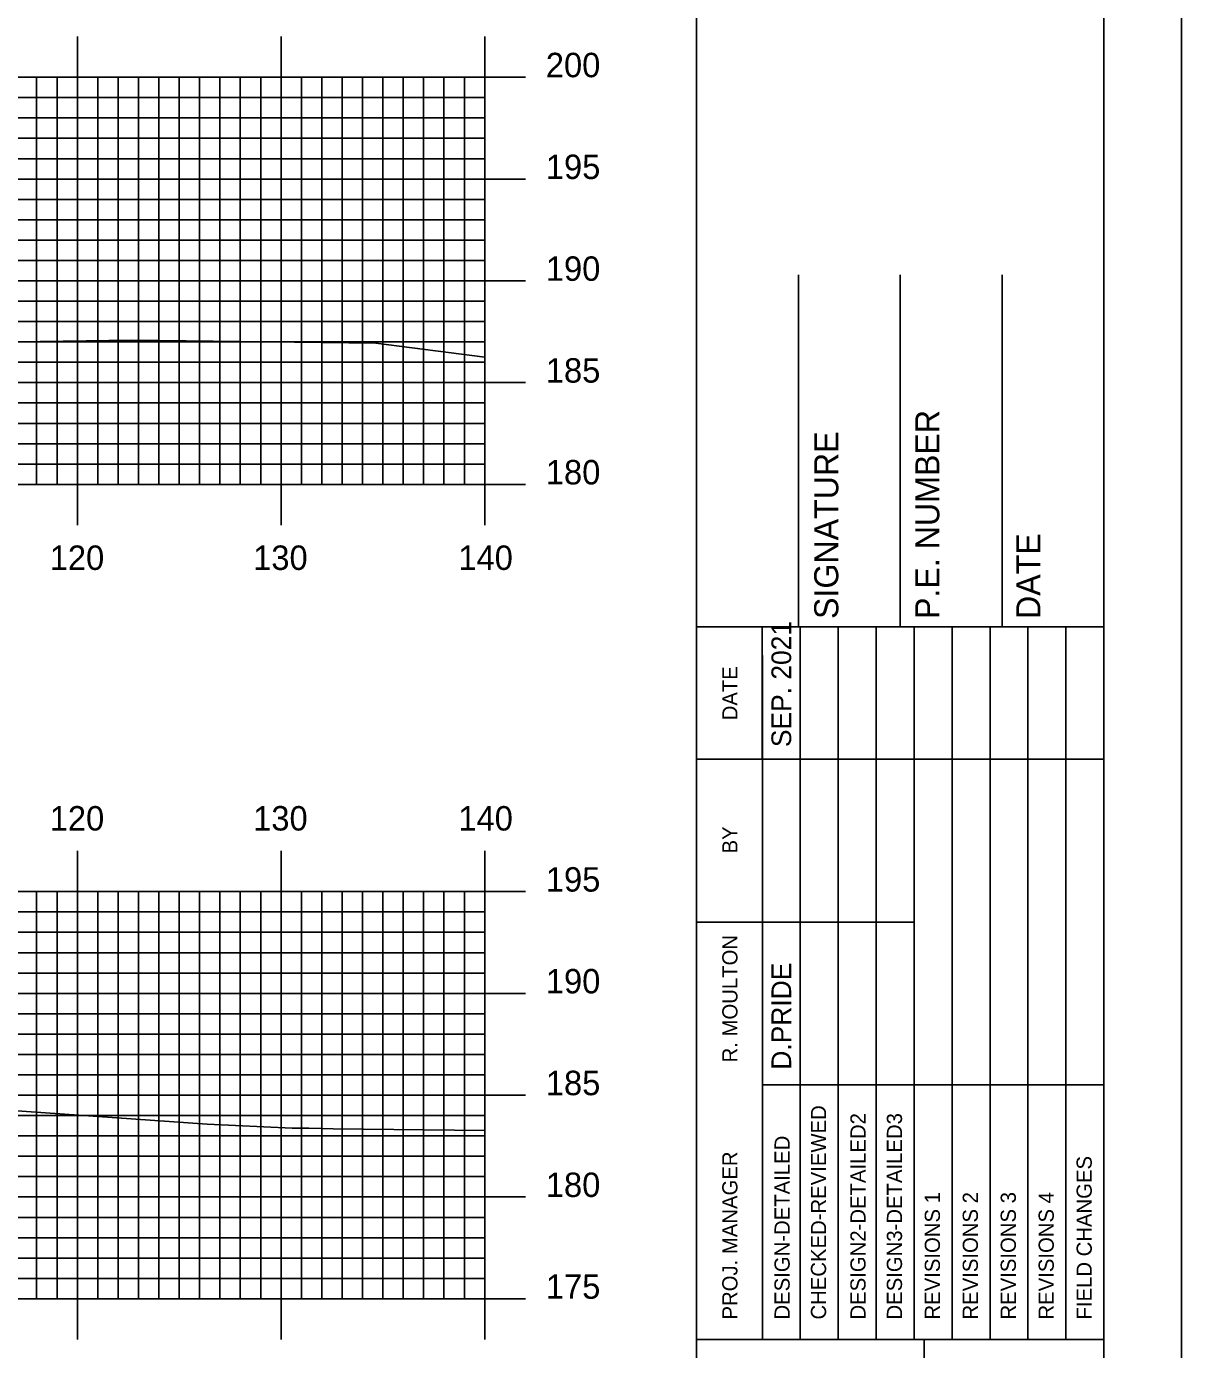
# Model space of a CAD drawing. Extents: x 1825147 to 1825490, y 442591 to 442811.
# Drawn here: x 1825429.9 to 1825486.6, y 442686.2 to 442751.2 of the extents above; entities that cross this region are included whole.
import ezdxf

# ---------------------------------------------------------------- set-up
doc = ezdxf.new("R2010")
doc.units = 0
for name, color, linetype in [('BORDER', 7, 'Continuous'), ('H_V ANNOTATION', 7, 'Continuous'), ('MAJOR', 7, 'Continuous'), ('MINOR', 7, 'Continuous'), ('PLOT BOUNDARY', 7, 'Continuous'), ('S_Roadway_Centerline', 7, 'Continuous')]:
    doc.layers.add(name, color=color, linetype=linetype)

msp = doc.modelspace()

# ---------------------------------------------------------------- linework, layer by layer
at = {"layer": 'BORDER'}
for p, q in [((1825462.761, 442596.665), (1825462.761, 442806.665)), ((1825467.761, 442721.671), (1825467.761, 442738.966)), ((1825472.761, 442721.671), (1825472.761, 442738.966)), ((1825477.761, 442721.671), (1825477.761, 442738.966)), ((1825462.761, 442721.671), (1825482.761, 442721.671)), ((1825462.761, 442686.671), (1825482.761, 442686.671)), ((1825473.943, 442616.671), (1825473.943, 442686.671))]:
    msp.add_line(p, q, dxfattribs=at)
msp.add_lwpolyline([(1825162.761, 442596.665), (1825482.761, 442596.665), (1825482.761, 442806.665), (1825162.761, 442806.665)], close=True, dxfattribs=at)
for points in [[(1825465.991, 442715.171), (1825465.991, 442721.671)], [(1825467.856, 442686.677), (1825467.856, 442721.671)], [(1825469.719, 442721.671), (1825469.719, 442686.677)], [(1825471.583, 442686.677), (1825471.583, 442721.671)], [(1825473.446, 442686.677), (1825473.446, 442721.671)], [(1825475.309, 442686.677), (1825475.309, 442721.671)], [(1825477.173, 442686.677), (1825477.173, 442721.671)], [(1825479.036, 442686.677), (1825479.036, 442721.671)], [(1825480.899, 442686.677), (1825480.899, 442721.671)], [(1825465.993, 442686.677), (1825465.993, 442720.259)], [(1825462.761, 442715.171), (1825482.761, 442715.171)], [(1825462.761, 442707.171), (1825465.993, 442707.171)], [(1825465.991, 442707.171), (1825473.444, 442707.171)], [(1825465.991, 442699.171), (1825482.761, 442699.171)]]:
    msp.add_lwpolyline(points, dxfattribs=at)
at = {"layer": 'MAJOR'}
for p, q in [((1825432.361, 442750.669), (1825432.361, 442748.665)), ((1825442.361, 442750.669), (1825442.361, 442748.665)), ((1825452.361, 442750.669), (1825452.361, 442748.665)), ((1825312.361, 442748.665), (1825452.361, 442748.665)), ((1825312.361, 442748.665), (1825452.361, 442748.665)), ((1825432.361, 442728.665), (1825432.361, 442748.665)), ((1825442.361, 442728.665), (1825442.361, 442748.665)), ((1825454.365, 442748.665), (1825450.357, 442748.665)), ((1825452.361, 442728.665), (1825452.361, 442748.665)), ((1825452.361, 442728.665), (1825452.361, 442748.665)), ((1825312.361, 442743.665), (1825452.361, 442743.665)), ((1825454.365, 442743.665), (1825450.357, 442743.665)), ((1825312.361, 442738.665), (1825452.361, 442738.665)), ((1825454.365, 442738.665), (1825450.357, 442738.665)), ((1825312.361, 442733.665), (1825452.361, 442733.665)), ((1825454.365, 442733.665), (1825450.357, 442733.665)), ((1825312.361, 442728.665), (1825452.361, 442728.665)), ((1825312.361, 442728.665), (1825452.361, 442728.665)), ((1825432.361, 442726.661), (1825432.361, 442728.665)), ((1825442.361, 442726.661), (1825442.361, 442728.665)), ((1825454.365, 442728.665), (1825450.357, 442728.665)), ((1825452.361, 442726.661), (1825452.361, 442728.665)), ((1825432.361, 442710.669), (1825432.361, 442708.665)), ((1825442.361, 442710.669), (1825442.361, 442708.665)), ((1825452.361, 442710.669), (1825452.361, 442708.665)), ((1825172.361, 442708.665), (1825452.361, 442708.665)), ((1825172.361, 442708.665), (1825452.361, 442708.665)), ((1825172.361, 442708.665), (1825452.361, 442708.665)), ((1825432.361, 442688.665), (1825432.361, 442708.665)), ((1825432.361, 442688.665), (1825432.361, 442708.665)), ((1825442.361, 442688.665), (1825442.361, 442708.665)), ((1825442.361, 442688.665), (1825442.361, 442708.665)), ((1825454.365, 442708.665), (1825450.357, 442708.665)), ((1825452.361, 442688.665), (1825452.361, 442708.665)), ((1825452.361, 442688.665), (1825452.361, 442708.665)), ((1825452.361, 442688.665), (1825452.361, 442708.665)), ((1825172.361, 442703.665), (1825452.361, 442703.665)), ((1825172.361, 442703.665), (1825452.361, 442703.665)), ((1825454.365, 442703.665), (1825450.357, 442703.665)), ((1825172.361, 442698.665), (1825452.361, 442698.665)), ((1825172.361, 442698.665), (1825452.361, 442698.665)), ((1825454.365, 442698.665), (1825450.357, 442698.665)), ((1825172.361, 442693.665), (1825452.361, 442693.665)), ((1825172.361, 442693.665), (1825452.361, 442693.665)), ((1825454.365, 442693.665), (1825450.357, 442693.665)), ((1825172.361, 442688.665), (1825452.361, 442688.665)), ((1825172.361, 442688.665), (1825452.361, 442688.665)), ((1825172.361, 442688.665), (1825452.361, 442688.665)), ((1825432.361, 442686.661), (1825432.361, 442688.665)), ((1825442.361, 442686.661), (1825442.361, 442688.665)), ((1825454.365, 442688.665), (1825450.357, 442688.665)), ((1825452.361, 442686.661), (1825452.361, 442688.665))]:
    msp.add_line(p, q, dxfattribs=at)
at = {"layer": 'MINOR'}
for p, q in [((1825430.361, 442728.665), (1825430.361, 442748.665)), ((1825431.361, 442728.665), (1825431.361, 442748.665)), ((1825433.361, 442728.665), (1825433.361, 442748.665)), ((1825434.361, 442728.665), (1825434.361, 442748.665)), ((1825435.361, 442728.665), (1825435.361, 442748.665)), ((1825436.361, 442728.665), (1825436.361, 442748.665)), ((1825437.361, 442728.665), (1825437.361, 442748.665)), ((1825438.361, 442728.665), (1825438.361, 442748.665)), ((1825439.361, 442728.665), (1825439.361, 442748.665)), ((1825440.361, 442728.665), (1825440.361, 442748.665)), ((1825441.361, 442728.665), (1825441.361, 442748.665)), ((1825443.361, 442728.665), (1825443.361, 442748.665)), ((1825444.361, 442728.665), (1825444.361, 442748.665)), ((1825445.361, 442728.665), (1825445.361, 442748.665)), ((1825446.361, 442728.665), (1825446.361, 442748.665)), ((1825447.361, 442728.665), (1825447.361, 442748.665)), ((1825448.361, 442728.665), (1825448.361, 442748.665)), ((1825449.361, 442728.665), (1825449.361, 442748.665)), ((1825450.361, 442728.665), (1825450.361, 442748.665)), ((1825451.361, 442728.665), (1825451.361, 442748.665)), ((1825312.361, 442747.665), (1825452.361, 442747.665)), ((1825452.361, 442747.665), (1825450.357, 442747.665)), ((1825312.361, 442746.665), (1825452.361, 442746.665)), ((1825452.361, 442746.665), (1825450.357, 442746.665)), ((1825312.361, 442745.665), (1825452.361, 442745.665)), ((1825452.361, 442745.665), (1825450.357, 442745.665)), ((1825312.361, 442744.665), (1825452.361, 442744.665)), ((1825452.361, 442744.665), (1825450.357, 442744.665)), ((1825312.361, 442742.665), (1825452.361, 442742.665)), ((1825452.361, 442742.665), (1825450.357, 442742.665)), ((1825312.361, 442741.665), (1825452.361, 442741.665)), ((1825452.361, 442741.665), (1825450.357, 442741.665)), ((1825312.361, 442740.665), (1825452.361, 442740.665)), ((1825452.361, 442740.665), (1825450.357, 442740.665)), ((1825312.361, 442739.665), (1825452.361, 442739.665)), ((1825452.361, 442739.665), (1825450.357, 442739.665)), ((1825312.361, 442737.665), (1825452.361, 442737.665)), ((1825452.361, 442737.665), (1825450.357, 442737.665)), ((1825312.361, 442736.665), (1825452.361, 442736.665)), ((1825452.361, 442736.665), (1825450.357, 442736.665)), ((1825312.361, 442735.665), (1825452.361, 442735.665)), ((1825452.361, 442735.665), (1825450.357, 442735.665)), ((1825312.361, 442734.665), (1825452.361, 442734.665)), ((1825452.361, 442734.665), (1825450.357, 442734.665)), ((1825312.361, 442732.665), (1825452.361, 442732.665)), ((1825452.361, 442732.665), (1825450.357, 442732.665)), ((1825312.361, 442731.665), (1825452.361, 442731.665)), ((1825452.361, 442731.665), (1825450.357, 442731.665)), ((1825312.361, 442730.665), (1825452.361, 442730.665)), ((1825452.361, 442730.665), (1825450.357, 442730.665)), ((1825312.361, 442729.665), (1825452.361, 442729.665)), ((1825452.361, 442729.665), (1825450.357, 442729.665)), ((1825430.361, 442688.665), (1825430.361, 442708.665)), ((1825430.361, 442688.665), (1825430.361, 442708.665)), ((1825431.361, 442688.665), (1825431.361, 442708.665)), ((1825431.361, 442688.665), (1825431.361, 442708.665)), ((1825433.361, 442688.665), (1825433.361, 442708.665)), ((1825433.361, 442688.665), (1825433.361, 442708.665)), ((1825434.361, 442688.665), (1825434.361, 442708.665)), ((1825434.361, 442688.665), (1825434.361, 442708.665)), ((1825435.361, 442688.665), (1825435.361, 442708.665)), ((1825435.361, 442688.665), (1825435.361, 442708.665)), ((1825436.361, 442688.665), (1825436.361, 442708.665)), ((1825436.361, 442688.665), (1825436.361, 442708.665)), ((1825437.361, 442688.665), (1825437.361, 442708.665)), ((1825437.361, 442688.665), (1825437.361, 442708.665)), ((1825438.361, 442688.665), (1825438.361, 442708.665)), ((1825438.361, 442688.665), (1825438.361, 442708.665)), ((1825439.361, 442688.665), (1825439.361, 442708.665)), ((1825439.361, 442688.665), (1825439.361, 442708.665)), ((1825440.361, 442688.665), (1825440.361, 442708.665)), ((1825440.361, 442688.665), (1825440.361, 442708.665)), ((1825441.361, 442688.665), (1825441.361, 442708.665)), ((1825441.361, 442688.665), (1825441.361, 442708.665)), ((1825443.361, 442688.665), (1825443.361, 442708.665)), ((1825443.361, 442688.665), (1825443.361, 442708.665)), ((1825444.361, 442688.665), (1825444.361, 442708.665)), ((1825444.361, 442688.665), (1825444.361, 442708.665)), ((1825445.361, 442688.665), (1825445.361, 442708.665)), ((1825445.361, 442688.665), (1825445.361, 442708.665)), ((1825446.361, 442688.665), (1825446.361, 442708.665)), ((1825446.361, 442688.665), (1825446.361, 442708.665)), ((1825447.361, 442688.665), (1825447.361, 442708.665)), ((1825447.361, 442688.665), (1825447.361, 442708.665)), ((1825448.361, 442688.665), (1825448.361, 442708.665)), ((1825448.361, 442688.665), (1825448.361, 442708.665)), ((1825449.361, 442688.665), (1825449.361, 442708.665)), ((1825449.361, 442688.665), (1825449.361, 442708.665)), ((1825450.361, 442688.665), (1825450.361, 442708.665)), ((1825450.361, 442688.665), (1825450.361, 442708.665)), ((1825451.361, 442688.665), (1825451.361, 442708.665)), ((1825451.361, 442688.665), (1825451.361, 442708.665)), ((1825172.361, 442707.665), (1825452.361, 442707.665)), ((1825172.361, 442707.665), (1825452.361, 442707.665)), ((1825452.361, 442707.665), (1825450.357, 442707.665)), ((1825172.361, 442706.665), (1825452.361, 442706.665)), ((1825172.361, 442706.665), (1825452.361, 442706.665)), ((1825452.361, 442706.665), (1825450.357, 442706.665)), ((1825172.361, 442705.665), (1825452.361, 442705.665)), ((1825172.361, 442705.665), (1825452.361, 442705.665)), ((1825452.361, 442705.665), (1825450.357, 442705.665)), ((1825172.361, 442704.665), (1825452.361, 442704.665)), ((1825172.361, 442704.665), (1825452.361, 442704.665)), ((1825452.361, 442704.665), (1825450.357, 442704.665)), ((1825172.361, 442702.665), (1825452.361, 442702.665)), ((1825172.361, 442702.665), (1825452.361, 442702.665)), ((1825452.361, 442702.665), (1825450.357, 442702.665)), ((1825172.361, 442701.665), (1825452.361, 442701.665)), ((1825172.361, 442701.665), (1825452.361, 442701.665)), ((1825452.361, 442701.665), (1825450.357, 442701.665)), ((1825172.361, 442700.665), (1825452.361, 442700.665)), ((1825172.361, 442700.665), (1825452.361, 442700.665)), ((1825452.361, 442700.665), (1825450.357, 442700.665)), ((1825172.361, 442699.665), (1825452.361, 442699.665)), ((1825172.361, 442699.665), (1825452.361, 442699.665)), ((1825452.361, 442699.665), (1825450.357, 442699.665)), ((1825172.361, 442697.665), (1825452.361, 442697.665)), ((1825172.361, 442697.665), (1825452.361, 442697.665)), ((1825452.361, 442697.665), (1825450.357, 442697.665)), ((1825172.361, 442696.665), (1825452.361, 442696.665)), ((1825172.361, 442696.665), (1825452.361, 442696.665)), ((1825452.361, 442696.665), (1825450.357, 442696.665)), ((1825172.361, 442695.665), (1825452.361, 442695.665)), ((1825172.361, 442695.665), (1825452.361, 442695.665)), ((1825452.361, 442695.665), (1825450.357, 442695.665)), ((1825172.361, 442694.665), (1825452.361, 442694.665)), ((1825172.361, 442694.665), (1825452.361, 442694.665)), ((1825452.361, 442694.665), (1825450.357, 442694.665)), ((1825172.361, 442692.665), (1825452.361, 442692.665)), ((1825172.361, 442692.665), (1825452.361, 442692.665)), ((1825452.361, 442692.665), (1825450.357, 442692.665)), ((1825172.361, 442691.665), (1825452.361, 442691.665)), ((1825172.361, 442691.665), (1825452.361, 442691.665)), ((1825452.361, 442691.665), (1825450.357, 442691.665)), ((1825172.361, 442690.665), (1825452.361, 442690.665)), ((1825172.361, 442690.665), (1825452.361, 442690.665)), ((1825452.361, 442690.665), (1825450.357, 442690.665)), ((1825172.361, 442689.665), (1825452.361, 442689.665)), ((1825172.361, 442689.665), (1825452.361, 442689.665)), ((1825452.361, 442689.665), (1825450.357, 442689.665))]:
    msp.add_line(p, q, dxfattribs=at)
at = {"layer": 'PLOT BOUNDARY'}
msp.add_lwpolyline([(1825146.574, 442590.547), (1825486.574, 442590.547), (1825486.574, 442810.547), (1825146.574, 442810.547)], close=True, dxfattribs=at)
at = {"layer": 'S_Roadway_Centerline'}
for points in [[(1825422.64, 442735.575), (1825435.035, 442735.754), (1825447.019, 442735.599), (1825452.361, 442734.919)], [(1825373.659, 442700.742), (1825375.488, 442699.72), (1825383.845, 442700.231), (1825387.263, 442699.545), (1825399.92, 442699.349), (1825410.057, 442699.219), (1825413.653, 442698.857), (1825420.747, 442698.508), (1825438.731, 442697.234), (1825442.904, 442697.049), (1825443.732, 442697.051), (1825444.919, 442697.008), (1825452.361, 442696.925)]]:
    msp.add_lwpolyline(points, dxfattribs=at)

# ---------------------------------------------------------------- texts
at = {"layer": 'BORDER'}
for s, height, p in [('P.E. NUMBER', 1.1811, (1825474.683, 442722.055)), ('SIGNATURE', 1.1811, (1825469.722, 442722.055)), ('DATE', 1.1811, (1825479.643, 442722.055)), ('SEP. 2021', 0.9691, (1825467.408, 442715.762)), ('DATE', 0.7428, (1825464.77, 442717.083)), ('BY', 0.7428, (1825464.77, 442710.541)), ('R. MOULTON', 0.7455, (1825464.771, 442700.276)), ('D.PRIDE', 0.9691, (1825467.408, 442699.917)), ('CHECKED-REVIEWED', 0.7455, (1825469.123, 442687.647)), ('DESIGN2-DETAILED2', 0.7455, (1825471.061, 442687.647)), ('DESIGN3-DETAILED3', 0.7455, (1825472.85, 442687.647)), ('DESIGN-DETAILED', 0.7455, (1825467.334, 442687.647)), ('PROJ. MANAGER', 0.7455, (1825464.77, 442687.647)), ('FIELD CHANGES', 0.7455, (1825482.167, 442687.647)), ('REVISIONS 1', 0.7455, (1825474.713, 442687.647)), ('REVISIONS 2', 0.7455, (1825476.576, 442687.647)), ('REVISIONS 3', 0.7455, (1825478.44, 442687.647)), ('REVISIONS 4', 0.7455, (1825480.303, 442687.647))]:
    msp.add_text(s, height=height, rotation=90, dxfattribs=at).set_placement(p)
at = {"layer": 'H_V ANNOTATION'}
for s, p in [('200', (1825455.361, 442748.665)), ('195', (1825455.361, 442743.665)), ('190', (1825455.361, 442738.665)), ('185', (1825455.361, 442733.665)), ('180', (1825455.361, 442728.665)), ('120', (1825431.002, 442724.465)), ('130', (1825440.991, 442724.465)), ('140', (1825451.066, 442724.465)), ('120', (1825431.002, 442711.665)), ('130', (1825440.991, 442711.665)), ('140', (1825451.066, 442711.665)), ('195', (1825455.361, 442708.665)), ('190', (1825455.361, 442703.665)), ('185', (1825455.361, 442698.665)), ('180', (1825455.361, 442693.665)), ('175', (1825455.361, 442688.665))]:
    msp.add_text(s, height=1.2, dxfattribs=at).set_placement(p)

doc.saveas('drawing.dxf')
